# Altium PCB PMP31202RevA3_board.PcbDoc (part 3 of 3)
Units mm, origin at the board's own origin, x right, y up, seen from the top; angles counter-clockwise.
Board outline 156.21 x 130.81 mm, 4 copper layers (Top Layer, Layer 2, Layer 3, Bottom Layer), stack 1.671 mm thick; 198 components, 74 nets, 489 pads, 691 vias.
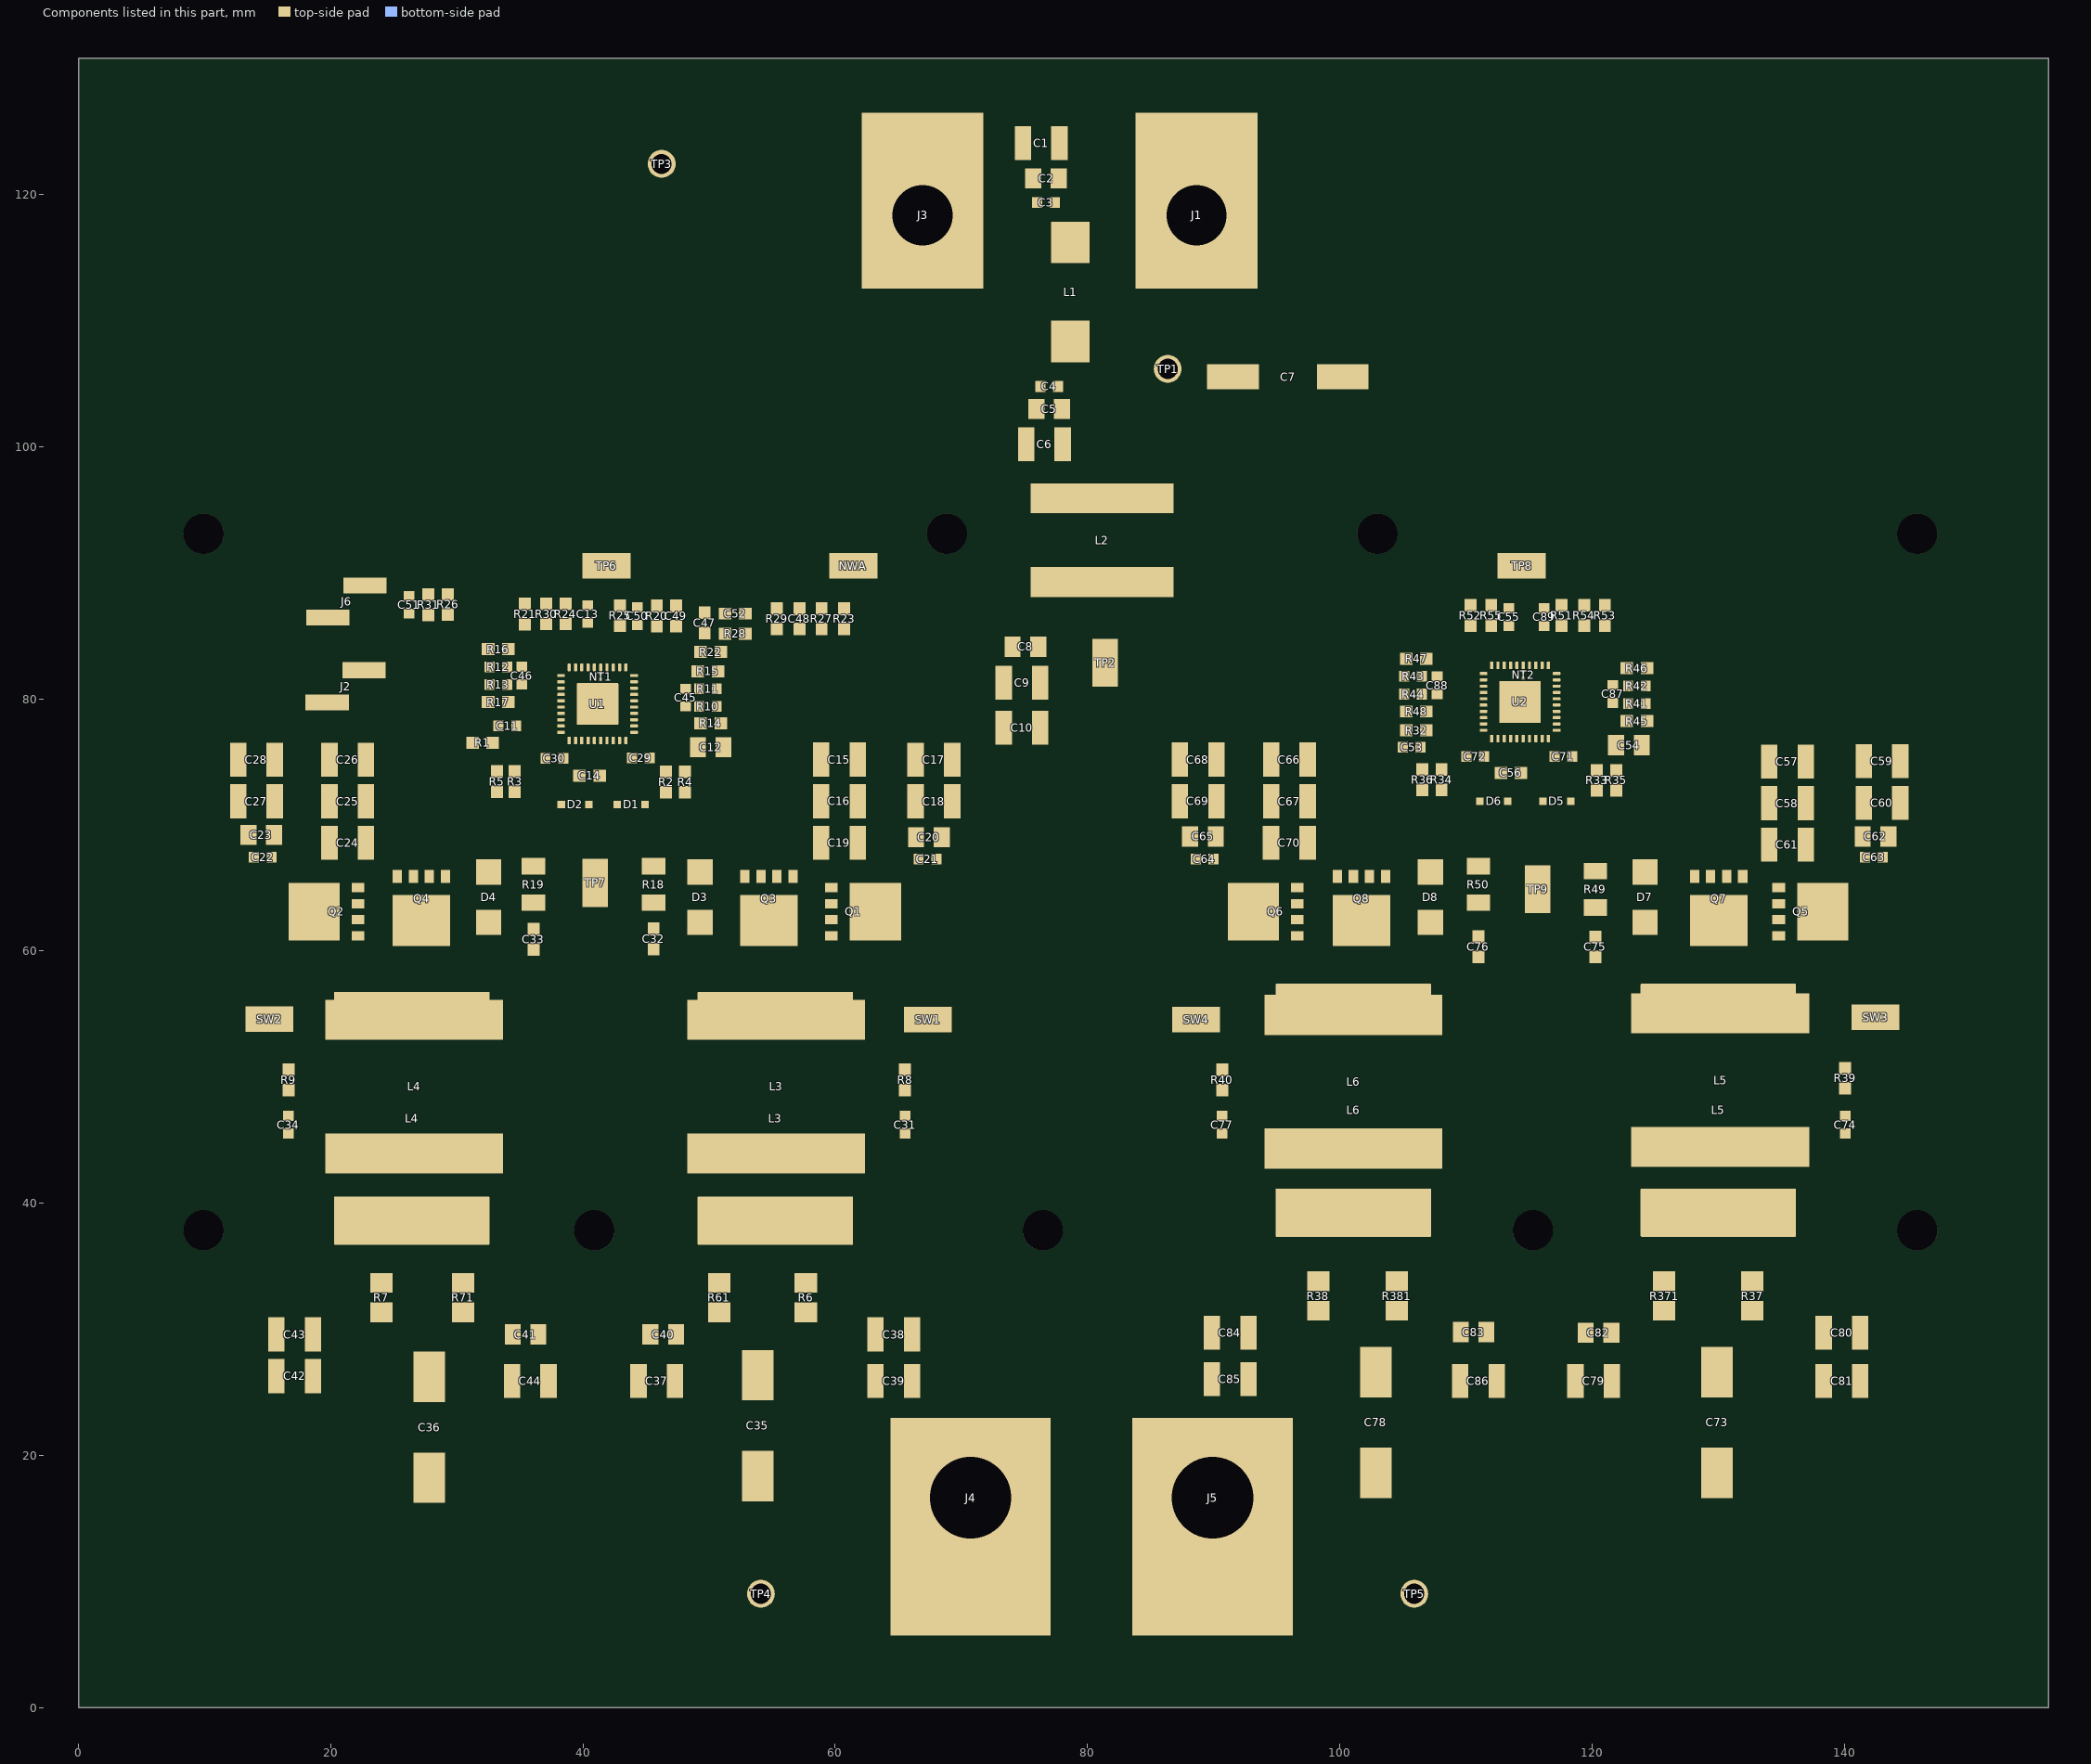
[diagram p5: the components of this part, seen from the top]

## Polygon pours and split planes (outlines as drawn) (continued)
NetC71_1 on Top Layer "TOP_LAYER_NETC71_1_P007" (solid, remove dead copper, pour order 7): 119.096,54.737 ccw(c121.636,54.737) 121.636,52.197 142.812,52.197 ccw(c142.812,54.737) 145.352,54.737 145.352,55.404 145.352,56.007 ccw(c142.812,56.007) 142.812,58.547 137.119,58.547 cw(c137.119,60.237) 135.429,60.237 135.429,65.119 ccw(c134.879,65.119) 134.879,65.669 134.666,65.669 ccw(c134.666,63.808) 133.35,65.124 132.917,64.691 cw(c132.207,65.402) 132.207,64.397 126.857,64.397 ccw(c126.857,63.123) 125.956,64.024 cw(c124.373,65.607) 124.373,63.368 123.822,63.368 ccw(c123.822,61.522) 121.975,61.522 121.975,60.882 cw(c121.285,60.882) 121.285,60.192 119.714,60.192 ccw(c119.714,59.574) 119.096,59.574
VOUT on Top Layer "TOP_LAYER_VOUT_P003" (solid, remove dead copper, pour order 3): 92.075,32.258 92.075,24.308 110.236,24.308 110.236,32.258
NetC77_2 on Top Layer "TOP_LAYER_NETC77_2_P005" (solid, remove dead copper, pour order 5): 92.057,34.435 93.468,33.024 108.071,33.024 110.226,35.179 110.226,45.247 108.991,46.482 93.27,46.482 92.057,45.269
NetC72_1 on Top Layer "TOP_LAYER_NETC72_1_P006" (solid, remove dead copper, pour order 6): 86.36,56.007 cw(c88.882,56.007) 88.882,58.529 94.54,58.529 ccw(c94.54,60.001) 96.012,60.001 96.012,63.815 cw(c96.459,63.815) 96.459,64.262 98.74,64.262 ccw(c98.74,64.562) 98.952,64.35 cw(c99.284,64.018) 99.284,64.487 106.46,64.487 cw(c106.46,61.947) 108.256,63.744 108.8,63.199 cw(c107.004,61.403) 109.544,61.403 109.544,60.999 ccw(c110.3,60.999) 110.3,60.242 111.473,60.242 cw(c111.473,59.04) 112.675,59.04 112.675,54.128 cw(c110.744,54.128) 110.744,52.197 88.265,52.197 cw(c88.265,54.102) 86.36,54.102
PGND on Top Layer "TOP_LAYER_PGND_P032" (solid, remove dead copper, pour order 32): 2.54,128.27 2.54,2.54 153.67,2.54 153.67,128.27
NetC29_1 on Top Layer "TOP_LAYER_NETC29_1_P031" (solid, remove dead copper, pour order 31): 68.834,52.197 ccw(c68.834,53.848) 70.485,53.848 70.485,56.007 ccw(c67.945,56.007) 67.945,58.547 61.722,58.547 cw(c61.722,60.01) 60.259,60.01 60.259,65.235 ccw(c59.825,65.235) 59.825,65.669 59.262,65.669 ccw(c59.262,64.768) 58.625,65.405 58.442,65.222 cw(c56.737,66.928) 56.737,64.516 52.548,64.516 ccw(c52.548,62.364) 51.026,63.886 cw(c49.777,65.134) 49.777,63.368 48.088,63.368 ccw(c48.088,62.374) 47.094,62.374 47.094,61.76 cw(c46.294,61.76) 46.294,60.96 45.118,60.96 ccw(c45.118,59.89) 44.048,59.89 44.048,54.737 ccw(c46.588,54.737) 46.588,52.197
AGND1 on Top Layer "TOP_LAYER_AGND1_P030" (solid, remove dead copper, pour order 30): 57.66,84.74 57.66,89.234 55.32,91.575 35.435,91.575 33.012,89.151 33.012,84.74
VIN on Top Layer "TOP_LAYER_VIN_P028" (solid, remove dead copper, pour order 28): 136.271,60.329 141.261,60.329 142.24,61.308 142.24,76.401 141.298,77.343 137.287,77.343 136.271,76.327
VIN on Top Layer "TOP_LAYER_VIN_P026" (solid, remove dead copper, pour order 26): 95.002,60.242 91.142,60.242 89.535,61.849 89.535,76.632 89.687,76.784 94.992,76.784 95.25,76.526 95.25,60.49
VIN on Top Layer "TOP_LAYER_VIN_P023" (solid, remove dead copper, pour order 23): 86.741,87.09 96.172,87.09 96.244,87.018 96.244,79.391 85.614,79.391 84.487,78.264 84.487,75.946 75.438,75.946 75.438,90.551 86.741,90.551
VIN on Top Layer "TOP_LAYER_VIN_P025" (solid, remove dead copper, pour order 25): 61.087,60.344 65.626,60.344 67.004,61.722 67.004,76.526 61.087,76.526
VOUT on Top Layer "TOP_LAYER_VOUT_P019" (solid, remove dead copper, pour order 19): 46.67,32.136 46.67,24.308 63.82,24.308 63.82,32.136
NetC31_2 on Top Layer "TOP_LAYER_NETC31_2_P017" (solid, remove dead copper, pour order 17): 62.974,46.001 63.82,45.155 63.82,34.737 61.971,32.888 47.993,32.888 46.67,34.212 46.67,45.165 47.506,46.001
NetC4_2 on Top Layer "TOP_LAYER_NETC4_2_P015" (solid, remove dead copper, pour order 15): 77.081,110.032 77.081,98.652 76.262,97.833 75.481,97.833 74.549,96.901 74.549,94.446 75.082,93.913 93.891,93.913 94.361,94.383 94.361,97.614 94.361,110.032 82.584,110.032
NetC1_1 on Top Layer "TOP_LAYER_NETC1_1_P013" (solid, remove dead copper, pour order 13): 77.089,126.229 77.089,114.103 78.99,112.202 93.98,112.202 93.98,128.27 79.13,128.27
VOUT on Top Layer "TOP_LAYER_VOUT_P012" (solid, remove dead copper, pour order 12): 17.861,32.136 17.861,24.257 35.052,24.257 35.052,32.136
NetC34_2 on Top Layer "TOP_LAYER_NETC34_2_P010" (solid, remove dead copper, pour order 10): 17.861,44.846 17.861,35.216 20.153,32.924 33.949,32.924 34.991,33.966 34.991,45.765 34.755,46.001 19.016,46.001
NetC30_1 on Top Layer "TOP_LAYER_NETC30_1_P009" (solid, remove dead copper, pour order 9): 20.267,52.262 13.754,52.262 cw(c13.754,53.76) 12.255,53.76 12.255,54.605 cw(c14.795,54.605) 12.999,56.401 14.782,58.184 cw(c16.578,56.388) 16.578,58.928 17.738,58.928 ccw(c17.738,61.468) 19.534,59.672 20.902,61.039 ccw(c19.106,62.835) 21.646,62.836 21.646,64.008 cw(c22.029,64.008) 21.653,64.083 cw(c22.082,64.087) 22.077,64.516 33.02,64.516 cw(c33.02,63.119) 34.417,63.119 34.417,61.627 ccw(c35.343,61.627) 35.343,60.701 36.068,60.701 cw(c36.068,59.258) 37.51,59.258 37.51,53.689 cw(c36.083,53.689) 36.083,52.262
VIN on Top Layer "TOP_LAYER_VIN_P008" (solid, remove dead copper, pour order 8): 20,60.35 20.701,61.052 20.701,65.742 20.701,76.504 14.782,76.504 14.782,61.214 15.646,60.35
PGND on Layer 3 "LAYER_3_PGND_P061" (solid, remove dead copper, pour order 61): 2.49,128.18 2.49,2.54 153.67,2.54 153.67,128.27
NetC4_2 on Layer 3 "LAYER_3_NETC4_2_P059" (solid, remove dead copper, pour order 59): 77.068,110.032 77.068,98.652 76.249,97.833 75.468,97.833 74.536,96.901 74.536,94.446 75.07,93.913 93.878,93.913 94.348,94.383 94.348,97.614 94.348,110.032 82.571,110.032
NetC1_1 on Layer 3 "LAYER_3_NETC1_1_P057" (solid, remove dead copper, pour order 57): 77.089,126.229 77.089,114.103 78.99,112.202 93.98,112.202 93.98,128.27 79.13,128.27
NetC29_1 on Layer 3 "LAYER_3_NETC29_1_P014" (solid, remove dead copper, pour order 14): 52.452,59.69 cw(c52.449,60.196) 51.942,60.196 51.942,64.201 cw(c52.456,64.201) 52.456,64.715 57.075,64.715 cw(c57.075,64.26) 57.53,64.26 57.53,60.303 cw(c56.868,60.352) 56.819,59.69
NetC30_1 on Layer 3 "LAYER_3_NETC30_1_P020" (solid, remove dead copper, pour order 20): 24.919,59.7 cw(c24.916,60.206) 24.41,60.206 24.41,64.211 cw(c24.924,64.211) 24.924,64.725 29.543,64.725 cw(c29.543,64.27) 29.998,64.27 29.998,60.313 cw(c29.336,60.362) 29.287,59.7
NetC72_1 on Layer 3 "LAYER_3_NETC72_1_P049" (solid, remove dead copper, pour order 49): 99.418,59.776 cw(c99.414,60.282) 98.908,60.282 98.908,64.288 cw(c99.422,64.288) 99.422,64.802 104.041,64.802 cw(c104.041,64.346) 104.496,64.346 104.496,60.389 cw(c103.834,60.438) 103.785,59.776
NetC71_1 on Layer 3 "LAYER_3_NETC71_1_P051" (solid, remove dead copper, pour order 51): 127.756,59.692 cw(c127.756,60.198) 127.25,60.198 127.25,64.203 cw(c127.764,64.203) 127.764,64.717 132.383,64.717 cw(c132.383,64.262) 132.838,64.262 132.838,60.305 cw(c132.176,60.354) 132.127,59.692
VOUT on Layer 3 "LAYER_3_VOUT_P055" (solid, remove dead copper, pour order 55): 17.861,31.623 17.861,2.54 139.7,2.54 139.7,31.623
VIN on Layer 3 "LAYER_3_VIN_P054" (solid, remove dead copper, pour order 54): 96.147,87.09 96.244,86.993 96.244,79.391 85.614,79.391 84.487,78.264 84.487,70.223 89.611,70.223 89.611,76.708 95.25,76.708 95.25,70.223 134.059,70.223 134.059,77.343 142.24,77.343 142.24,50.504 12.768,50.504 12.768,76.708 21.288,76.708 21.288,70.223 59.125,70.223 59.125,76.776 67.004,76.776 67.004,70.223 75.481,70.223 75.481,87.09
NetC4_2 on Bottom Layer "BOTTOM_LAYER_NETC4_2_P022" (solid, remove dead copper, pour order 22): 77.068,110.032 77.068,98.652 76.249,97.833 75.468,97.833 74.536,96.901 74.536,94.446 75.07,93.913 93.878,93.913 94.348,94.383 94.348,97.614 94.348,110.032 82.571,110.032
NetC1_1 on Bottom Layer "BOTTOM_LAYER_NETC1_1_P021" (solid, remove dead copper, pour order 21): 77.089,126.229 77.089,114.103 78.99,112.202 93.98,112.202 93.98,128.27 79.13,128.27
VIN on Bottom Layer "BOTTOM_LAYER_VIN_P027" (solid, remove dead copper, pour order 27): 90.739,60.639 90.739,65.856 95.483,65.856 95.483,60.639
VIN on Bottom Layer "BOTTOM_LAYER_VIN_P029" (solid, remove dead copper, pour order 29): 135.964,60.526 135.964,65.743 140.709,65.743 140.709,60.526
VIN on Bottom Layer "BOTTOM_LAYER_VIN_P033" (solid, remove dead copper, pour order 33): 60.856,60.526 60.856,65.743 65.601,65.743 65.601,60.526
VIN on Bottom Layer "BOTTOM_LAYER_VIN_P034" (solid, remove dead copper, pour order 34): 16.254,60.501 16.254,65.718 20.999,65.718 20.999,60.501
VOUT on Bottom Layer "BOTTOM_LAYER_VOUT_P042" (solid, remove dead copper, pour order 42): 120.875,31.75 139.108,31.75 139.108,24.257 120.947,24.257
VOUT on Bottom Layer "BOTTOM_LAYER_VOUT_P037" (solid, remove dead copper, pour order 37): 92.118,31.75 92.118,24.308 110.279,24.308 110.279,31.75
VOUT on Bottom Layer "BOTTOM_LAYER_VOUT_P036" (solid, remove dead copper, pour order 36): 46.627,31.623 46.627,24.308 63.777,24.308 63.777,31.623 60.536,31.623
VOUT on Bottom Layer "BOTTOM_LAYER_VOUT_P035" (solid, remove dead copper, pour order 35): 17.866,31.496 17.866,24.257 35.057,24.257 35.057,31.496
PGND on Bottom Layer "BOTTOM_LAYER_PGND_P060" (solid, remove dead copper, pour order 60): 2.49,128.27 153.67,128.27 153.67,2.54 2.578,2.54
NetC71_1 on Bottom Layer "BOTTOM_LAYER_NETC71_1_P058" (solid, remove dead copper, pour order 58): 119.032,54.737 ccw(c121.572,54.737) 121.572,52.197 142.748,52.197 ccw(c142.748,54.737) 145.288,54.737 145.288,55.404 145.288,56.007 ccw(c142.748,56.007) 142.748,58.547 137.055,58.547 cw(c137.055,60.237) 135.365,60.237 135.365,65.119 ccw(c134.815,65.119) 134.815,65.669 134.602,65.669 ccw(c134.602,63.808) 133.286,65.124 132.853,64.691 cw(c132.143,65.402) 132.143,64.397 126.793,64.397 ccw(c126.793,63.123) 125.892,64.024 cw(c124.309,65.607) 124.309,63.368 123.758,63.368 ccw(c123.758,61.522) 121.911,61.522 121.911,60.882 cw(c121.221,60.882) 121.221,60.192 119.65,60.192 ccw(c119.65,59.574) 119.032,59.574
NetC72_1 on Bottom Layer "BOTTOM_LAYER_NETC72_1_P056" (solid, remove dead copper, pour order 56): 86.344,56.007 cw(c88.866,56.007) 88.866,58.529 94.524,58.529 ccw(c94.524,60.001) 95.996,60.001 95.996,63.815 cw(c96.443,63.815) 96.443,64.262 98.724,64.262 ccw(c98.724,64.562) 98.936,64.35 cw(c99.268,64.018) 99.268,64.487 106.443,64.487 cw(c106.443,61.947) 108.239,63.744 108.784,63.199 cw(c106.988,61.403) 109.528,61.403 109.528,60.999 ccw(c110.284,60.999) 110.284,60.242 111.457,60.242 cw(c111.457,59.04) 112.659,59.04 112.659,54.128 cw(c110.728,54.128) 110.728,52.197 88.249,52.197 cw(c88.249,54.102) 86.344,54.102
NetC29_1 on Bottom Layer "BOTTOM_LAYER_NETC29_1_P047" (solid, remove dead copper, pour order 47): 68.835,52.197 ccw(c68.835,53.848) 70.486,53.848 70.486,56.007 ccw(c67.946,56.007) 67.946,58.547 61.723,58.547 cw(c61.723,60.01) 60.26,60.01 60.26,65.235 ccw(c59.826,65.235) 59.826,65.669 59.263,65.669 ccw(c59.263,64.768) 58.626,65.405 58.443,65.222 cw(c56.738,66.928) 56.738,64.516 52.548,64.516 ccw(c52.548,62.364) 51.027,63.886 cw(c49.778,65.134) 49.778,63.368 48.089,63.368 ccw(c48.089,62.374) 47.095,62.374 47.095,61.76 cw(c46.295,61.76) 46.295,60.96 45.119,60.96 ccw(c45.119,59.89) 44.049,59.89 44.049,54.737 ccw(c46.589,54.737) 46.589,52.197
NetC30_1 on Bottom Layer "BOTTOM_LAYER_NETC30_1_P044" (solid, remove dead copper, pour order 44): 20.271,52.241 13.758,52.241 cw(c13.758,53.74) 12.259,53.74 12.259,54.584 cw(c14.799,54.584) 13.003,56.38 14.787,58.163 cw(c16.583,56.367) 16.583,58.907 17.743,58.907 ccw(c17.743,61.447) 19.539,59.651 20.906,61.019 ccw(c19.11,62.815) 21.65,62.815 21.65,63.987 cw(c22.034,63.987) 21.658,64.062 cw(c22.086,64.067) 22.082,64.495 33.024,64.495 cw(c33.024,63.098) 34.421,63.098 34.421,61.606 ccw(c35.347,61.606) 35.347,60.68 36.072,60.68 cw(c36.072,59.238) 37.515,59.238 37.515,53.668 cw(c36.087,53.668) 36.087,52.241
NetC30_1 on Layer 2 "LAYER_2_NETC30_1_P052" (solid, remove dead copper, pour order 52): 24.919,59.7 cw(c24.916,60.206) 24.41,60.206 24.41,64.211 cw(c24.924,64.211) 24.924,64.725 29.543,64.725 cw(c29.543,64.27) 29.998,64.27 29.998,60.313 cw(c29.336,60.362) 29.287,59.7
NetC29_1 on Layer 2 "LAYER_2_NETC29_1_P048" (solid, remove dead copper, pour order 48): 52.448,59.701 cw(c52.444,60.207) 51.938,60.207 51.938,64.213 cw(c52.452,64.213) 52.452,64.727 57.071,64.727 cw(c57.071,64.271) 57.526,64.271 57.526,60.314 cw(c56.864,60.363) 56.815,59.701
NetC72_1 on Layer 2 "LAYER_2_NETC72_1_P043" (solid, remove dead copper, pour order 43): 99.433,59.782 cw(c99.43,60.288) 98.924,60.288 98.924,64.293 cw(c99.438,64.293) 99.438,64.807 104.057,64.807 cw(c104.057,64.352) 104.512,64.352 104.512,60.395 cw(c103.85,60.444) 103.8,59.782
NetC71_1 on Layer 2 "LAYER_2_NETC71_1_P041" (solid, remove dead copper, pour order 41): 127.763,59.692 cw(c127.76,60.198) 127.254,60.198 127.254,64.203 cw(c127.768,64.203) 127.768,64.717 132.387,64.717 cw(c132.387,64.262) 132.842,64.262 132.842,60.305 cw(c132.18,60.354) 132.131,59.692
VIN on Layer 2 "LAYER_2_VIN_P018" (solid, remove dead copper, pour order 18): 135.99,60.552 135.99,65.769 140.734,65.769 140.734,60.552
VIN on Layer 2 "LAYER_2_VIN_P045" (solid, remove dead copper, pour order 45): 90.752,60.501 90.752,65.718 95.497,65.718 95.497,60.501
VIN on Layer 2 "LAYER_2_VIN_P050" (solid, remove dead copper, pour order 50): 60.831,60.552 60.831,65.769 65.576,65.769 65.576,60.552
VIN on Layer 2 "LAYER_2_VIN_P046" (solid, remove dead copper, pour order 46): 16.317,60.569 16.317,65.786 21.061,65.786 21.061,60.569
PGND on Layer 2 "LAYER_2_PGND_P053" (solid, remove dead copper, pour order 53): 2.54,128.27 153.67,128.27 153.67,2.54 2.54,2.54

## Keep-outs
Keep-Out Layer:
  text ".Layer_Name" at 8.306,-53.556 h1.52

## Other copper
Top Layer:
  pour cut-out: 135.63,65.58 136.271,65.58 136.271,60.293 135.504,60.293
  pour cut-out: 127.473,65.278 132.526,65.278 132.526,64.769 127.448,64.769
  pour cut-out: 99.181,65.278 104.277,65.278 104.277,64.762 99.244,64.762
  pour cut-out: 95.377,65.913 95.377,65.914 95.996,65.914 95.996,63.754 95.412,63.754
  pour cut-out: 112.649,77.851 112.649,81.431 112.014,81.431 112.014,77.851
  pour cut-out: 115.951,81.534 115.951,78.081 116.573,78.081 116.573,81.431
  pour cut-out: 112.027,81.431 112.027,82.057 116.573,82.057 116.573,81.431
  pour cut-out: 112.027,78.081 112.027,77.483 116.573,77.483 116.573,78.081
  pour cut-out: 52.305,65.377 52.305,64.528 56.896,64.528 56.896,65.362
  pour cut-out: 60.305,60.636 60.305,65.669 60.958,65.669 60.958,60.779
  pour cut-out: 20.745,60.823 21.462,60.823 21.462,65.786 20.745,65.786
  pour cut-out: 24.628,65.233 24.628,64.516 29.591,64.516 29.591,65.233
  pour cut-out: 42.897,76.979 43.747,76.979 43.747,82.13 42.902,82.13
  pour cut-out: 38.579,76.979 39.429,76.979 39.429,82.13 38.584,82.13
  pour cut-out: 38.625,82.198 38.625,81.348 43.776,81.348 43.776,82.193
  pour cut-out: 38.608,77.851 38.608,77.001 43.759,77.001 43.759,77.846
  text ".Layer_Name" at 8.306,-53.556 h1.52
Bottom Layer:
  text ".Layer_Name" at 8.306,-53.556 h1.52

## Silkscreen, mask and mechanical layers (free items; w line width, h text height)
Top Overlay:
  text "GND" at 52.324,120.536 h2
  text "IN" at 97.79,119.634 h2
  text "'.PRJ_Number'.PCB_Rev" at 13.843,10.795 h2
  text "VOUT" at 40.24,8.636 h2
  text "GND" at 111.752,8.255 h2
  text ".Layer_Name" at 8.306,-53.556 h1.52
Bottom Overlay:
  lines w0.3: 3.029,26.905 3.029,101.905 153.029,101.905 153.029,26.905 3.029,26.905
  text ".Layer_Name" at 8.306,-53.556 h1.52
Top Paste:
  text ".Layer_Name" at 8.306,-53.556 h1.52
Bottom Paste:
  text ".Layer_Name" at 8.306,-53.556 h1.52
Top Solder:
  rectangle: 68.527,59.897 73.292,64.753
  text ".Layer_Name" at 8.306,-53.556 h1.52
  text ".Layer_Name" at 8.306,-53.556 h1.52
Bottom Solder:
  region: 1.169,103.81 154.737,103.81 154.737,25.298 1.168,25.298
  text "'.PRJ_Number'.PCB_Rev" at 35.177,6.477 h3
  text ".Layer_Name" at 8.306,-53.556 h1.52
Drill Guide:
  text ".Layer_Name" at 8.306,-53.556 h1.52
M1 Board Outline:
  the board outline again, w0.254
  text ".Layer_Name" at 8.306,-53.556 h1.52
M2 Board Dimensions:
  rectangle: 182.65,-37.735 185.825,-34.56
  rectangle: 185.825,-40.91 195.35,-37.735
  lines w0.178: 182.65,-37.735 208.05,-37.735 ; 185.825,-40.91 185.825,-34.56 ; 189,-40.91 189,-34.56 ; 195.35,-40.91 195.35,-34.56 ; 201.7,-40.91 201.7,-34.56 ; 182.65,-40.91 208.05,-40.91 208.05,-34.56 182.65,-34.56 182.65,-40.91
  text "'.Print_Date' '.Print_Time'" at 98.044,134.318 h5
  text ".Layer_Name" at 8.306,-53.556 h1.52
M3 3D STEP Top:
  text ".Layer_Name" at 8.306,-53.556 h1.52
M4 3D STEP Bottom:
  text ".Layer_Name" at 8.306,-53.556 h1.52
M5 Assembly Top:
  lines w0.254: -13.767,-55.376 153.873,-55.376 ; -13.767,-50.212 153.924,-50.212 ; -13.767,-45.047 -13.767,-60.541 87.96,-60.541 153.924,-60.541 153.924,-45.047 -13.754,-45.047 -13.754,-60.541 26.264,-60.541 ; 48.844,-60.541 48.844,-45.047 ; 81.026,-50.212 81.026,-45.047 ; 102.362,-50.212 102.362,-45.047 ; 118.161,-60.706 118.161,-55.554
  text "COMPONENTS MARKED 'DNP' SHOULD NOT BE POPULATED." at 212.949,-38.84 h1.52
  text "ASSEMBLY VARIANT:" at 212.936,-41.774 h1.52
  text ".VariantName" at 239.251,-41.774 h1.52
  text "PCB VIEWED FROM TOP SIDE" at -12.154,-48.404 h1.52
  text "BOARD #:" at 50.749,-48.404 h1.52
  text ".PRJ_Number" at 64.605,-48.404 h1.52
  text "REV:" at 86.055,-48.404 h1.52
  text ".PCB_Rev" at 93.459,-48.404 h1.52
  text "SVN REV:" at 107.34,-48.404 h1.52
  text ".VersionControl_RevNumber" at 120.193,-48.404 h1.52
  text "TID #:" at 50.749,-53.569 h1.52
  text ".TID" at 64.605,-53.569 h1.52
  text "PLOT NAME =" at -12.154,-58.784 h1.52
  text ".plot_File_Name" at 8.306,-58.784 h1.52
  text "GENERATED    :" at 50.8,-58.784 h1.52
  text ".Print_Date" at 72.885,-58.784 h1.52
  text ".Print_Time" at 91.402,-58.784 h1.52
  text "TEXAS INSTRUMENTS" at 123.52,-58.784 h1.52
M6 Assembly Bottom:
  lines w0.254: -13.779,-50.224 153.911,-50.224 ; -13.729,-55.389 153.911,-55.389 ; 21.984,-60.719 21.984,-55.567 ; 37.782,-50.224 37.782,-45.06 ; 59.118,-50.224 59.118,-45.06 ; 91.3,-60.554 91.3,-45.06 ; 113.881,-60.554 153.899,-60.554 153.899,-45.06 -13.779,-45.06 -13.779,-60.554 52.184,-60.554 153.911,-60.554 153.911,-45.06
  text "COMPONENTS MARKED 'DNP' SHOULD NOT BE POPULATED." at 252.65,-29.75 h1.52
  text ".VariantName" at 226.123,-32.774 h1.52
  text "ASSEMBLY VARIANT:" at 252.514,-32.774 h1.52
  text ".VersionControl_RevNumber" at 19.952,-48.417 h1.52
  text "SVN REV:" at 32.804,-48.417 h1.52
  text ".PCB_Rev" at 46.685,-48.417 h1.52
  text "REV:" at 54.089,-48.417 h1.52
  text ".PRJ_Number" at 75.54,-48.417 h1.52
  text "BOARD #:" at 89.395,-48.417 h1.52
  text "PCB VIEWED FROM BOTTOM SIDE" at 152.298,-48.417 h1.52
  text ".TID" at 75.54,-53.581 h1.52
  text "TID #:" at 89.395,-53.581 h1.52
  text "TEXAS INSTRUMENTS" at 16.624,-58.797 h1.52
  text ".Print_Time" at 48.743,-58.797 h1.52
  text ".Print_Date" at 67.259,-58.797 h1.52
  text "GENERATED    :" at 89.344,-58.797 h1.52
  text ".plot_File_Name" at 131.839,-58.797 h1.52
  text "PLOT NAME =" at 152.298,-58.797 h1.52
M9 Title Sheet:
  drawing of 57 lines, arcs and shapes, not listed
  text "1" at 12.442,172.377 h1.78
  text "2" at 75.832,172.377 h1.78
  text "3" at 139.061,172.377 h1.78
  text "4" at 202.73,172.377 h1.78
  text "5" at 266.205,172.377 h1.78
  text "6" at 329.832,172.377 h1.78
  text "A" at -16.929,143.345 h1.78
  text "A" at 358.991,143.345 h1.78
  text "B" at -16.929,82.893 h1.78
  text "B" at 358.991,82.893 h1.78
  text "C" at -16.929,22.568 h1.78
  text "C" at 358.991,22.568 h1.78
  text "PROJECT TITLE:" at 281.775,-24.701 h1.14
  text ".PRJ_Title" at 283.045,-28.088 h1.78
  text "DESIGNED FOR:" at 281.775,-32.347 h1.14
  text ".PRJ_Customer" at 283.045,-35.903 h1.78
  text "D" at -16.929,-37.63 h1.78
  text "D" at 358.991,-37.63 h1.78
  text "FILE NAME:" at 281.775,-39.967 h1.14
  text ".PCB_File_Name_No_Path" at 283.045,-43.015 h1.78
  text "Texas Instruments (TI) and/or its licensors do not warrant the accuracy or completeness of this specification" at 155.55,-47.126 h1.14
  text "ENGINEER:" at 281.775,-47.333 h1.14
  text "LAYOUT BY:" at 320.002,-47.333 h1.14
  text "or any information contained therein. TI and/or its licensors do not warrant that this design will meet" at 154.407,-49.987 h1.14
  text ".PRJ_Engineer" at 283.045,-51.27 h1.78
  text ".PCB_Layout" at 321.285,-51.27 h1.78
  text "the specifications, will be suitable for your application or fit for any particular purpose, or will operate in" at 154.407,-52.849 h1.14
  text ".Layer_Name" at 8.306,-53.556 h1.52
  text "ALTIUM DESIGNER VERSION:" at 320.002,-55.207 h1.14
  text "an implementation. TI and/or its licensors do not warrant that the design is production worthy. You should" at 154.407,-55.711 h1.14
  text "completely validate and test your design implementation to confirm the system functionality for your application." at 155.55,-58.572 h1.14
  text ".print_Scale" at 283.045,-58.593 h1.78
  text ".Application_BuildNumber" at 321.285,-58.593 h1.78
  text "1" at 12.442,-63.843 h1.78
  text "2" at 75.832,-63.843 h1.78
  text "3" at 139.061,-63.843 h1.78
  text "4" at 202.73,-63.843 h1.78
  text "5" at 266.205,-63.843 h1.78
  text "6" at 329.832,-63.843 h1.78
M10 Fab Notes:
  drawing of 189 lines, arcs and shapes, not listed
  text "DESIGN INFORMATION" at 308.153,129.697 h1.52
  text "MIN. TRACK WIDTH:" at 291.781,126.341 h1.52
  text "8" at 319.626,126.341 h1.52
  text "MIL" at 323.557,126.341 h1.52
  text "MIN. CLEARANCE:" at 291.781,123.188 h1.52
  text "0.2" at 318.102,123.188 h1.52
  text "mm" at 323.557,123.188 h1.52
  text "MIN. VIA PAD SIZE:" at 291.781,120.035 h1.52
  text "24" at 318.864,120.035 h1.52
  text "MIL" at 323.557,120.035 h1.52
  text "0.05mm (2MIL)" at 309.434,116.736 h1.52
  text "MINIMUM ANNULAR RING" at 283.419,116.527 h1.52
  text "EXTERNAL" at 327.418,116.527 h1.52
  text "PER" at 288.499,113.73 h1.52
  text "IPC-D-275 CLASS 2 LEVEL C" at 294.087,113.73 h1.52
  text "MIL, HOLES" at 331.888,111.178 h1.52
  text "+/-" at 321.92,110.959 h1.52
  text "+/-" at 343.611,110.959 h1.52
  text "REGISTRATION TOLERANCES:" at 283.419,110.932 h1.52
  text "METAL" at 313.893,110.932 h1.52
  text "5" at 328.529,110.933 h1.52
  text "3" at 349.687,110.933 h1.52
  text "MIL" at 352.64,110.932 h1.52
  text "HOLE SIZE TOLERANCE (UNLESS OTHERWISE SPECIFIED):" at 283.419,108.435 h1.52
  text "+/-" at 343.611,108.362 h1.52
  text "3" at 349.687,108.335 h1.52
  text "MIL" at 352.64,108.335 h1.52
  text "MATERIAL:" at 281.52,104.839 h1.52
  text "FR-4 High Tg" at 306.576,101.574 h1.52
  text "X" at 302.907,101.372 h1.52
  text "FR-408" at 292.213,101.257 h1.52
  text "OTHER" at 330.008,101.257 h1.52
  text "62 MIL (1.6mm) +/-10%" at 300.344,97.624 h1.52
  text "X" at 297.293,97.562 h1.52
  text "THICKNESS:" at 283.419,97.415 h1.52
  text "OTHER" at 332.98,97.415 h1.52
  text "TOLERANCE:" at 283.419,93.902 h1.52
  text "X" at 304.964,93.902 h1.52
  text "ANSI IPC-6012 TYPE 3 CLASS 2" at 309.486,93.902 h1.52
  text "OTHER +/-" at 309.485,90.239 h1.52
  text "BOW & TWIST:" at 283.419,86.552 h1.52
  text "X" at 304.964,86.552 h1.52
  text "ANSI IPC-6012 TYPE 3 CLASS 2" at 309.486,86.552 h1.52
  text "OTHER +/-" at 309.485,82.826 h1.52
  text "DRILLING:" at 281.52,79.508 h1.52
  text "NC_DRILL FILES" at 326.249,76.836 h1.52
  text "REFERENCE:" at 283.419,76.736 h1.52
  text "X" at 300.113,76.734 h1.52
  text "AS SHOWN" at 304.634,76.736 h1.52
  text "X" at 322.998,76.736 h1.52
  text "OTHER" at 333.818,73.123 h1.52
  text "PTH COPPER THICKNESS:" at 283.411,73.033 h1.52
  text "X" at 312.347,73.033 h1.52
  text "20-30 um" at 315.598,73.033 h1.52
  text "BOARD FINISH:" at 281.52,69.284 h1.52
  text "SILKSCREEN:" at 285.462,66.487 h1.52
  text "X" at 309.79,66.487 h1.52
  text "TOP" at 312.762,66.487 h1.52
  text "X" at 322.744,66.487 h1.52
  text "BOTTOM" at 325.741,66.487 h1.52
  text "SILKSCREEN COLOR:" at 285.462,62.545 h1.52
  text "X" at 309.765,62.545 h1.52
  text "WHITE" at 312.762,62.545 h1.52
  text "OTHER" at 325.741,62.545 h1.52
  text "X" at 313.092,58.902 h1.52
  text "GREEN" at 316.089,58.902 h1.52
  text "OTHER" at 331.786,58.902 h1.52
  text "SOLDER RESIST COLOR:" at 285.462,58.727 h1.52
  text "X" at 313.092,54.984 h1.52
  text "MATTE" at 316.089,54.984 h1.52
  text "SEMI-GLOSS" at 331.775,54.967 h1.52
  text "IMMERSION GOLD (ENIG)" at 308.469,50.595 h1.52
  text "ENEPIG" at 342.443,50.412 h1.52
  text "SURFACE FINISH:" at 281.52,50.386 h1.52
  text "X" at 303.948,50.386 h1.52
  text "IMM. TIN/SILVER OR EQUIV" at 289.89,46.899 h1.52
  text "OTHER" at 326.249,46.799 h1.52
  text "ARRAY/PANEL:" at 281.52,42.852 h1.52
  text "CUT AND TRIM PER M1 BOARD OUTLINE" at 308.469,42.643 h1.52
  text "N.C. ROUTE" at 308.469,39.19 h1.52
  text "X" at 325.945,39.19 h1.52
  text "V. SCORE" at 330.466,39.19 h1.52
  text "CERTIFICATION:" at 281.52,35.91 h1.52
  text "MATERIALS AND WORKMANSHIP FOR ALL PCBS" at 299.935,35.91 h1.52
  text "TO MEET OR EXCEED THE REQUIREMENTS OF:" at 299.935,33.521 h1.52
  text "X" at 290.728,30.253 h1.52
  text "ANSI IPC-A-600F CLASS ->" at 293.979,30.253 h1.52
  text "X" at 335.838,30.253 h1.52
  text "2" at 338.632,30.253 h1.52
  text "1" at 330.631,30.215 h1.52
  text "3" at 347.623,30.215 h1.52
  text "X" at 311.352,26.502 h1.52
  text "RoHS" at 314.603,26.502 h1.52
  text "OTHER" at 330.971,26.502 h1.52
  text "PER ORDER" at 341.057,26.502 h1.52
  text "ALL BOARDS MUST MEET OR EXCEED UL94-V0 REQUIREMENTS." at 282.219,22.595 h1.52
  text "PCB MUST BEAR THE UL94V-0 UL REGISTERED MATERIAL ID NUMBER" at 282.219,19.647 h1.52
  text "ADDITIONAL REQUIREMENTS:" at 281.52,15.344 h1.52
  text "MICROSECTION:" at 283.419,12.623 h1.52
  text "YES" at 306.425,12.623 h1.52
  text "REQUIRED" at 328.307,8.957 h1.52
  text "BARE BOARD ELEC. TEST:" at 283.419,8.884 h1.52
  text "NONE" at 316.585,8.884 h1.52
  text "X" at 325.31,8.884 h1.52
  text "PER ORDER" at 343.343,8.884 h1.52
  text "XX MIL VIAS REQUIRE NON-CONDUCTIVE FILL AND PLANARIZE" at 287.69,3.678 h1.5
  text "XX MIL VIAS REQUIRE CONDUCTIVE FILL AND PLANARIZE" at 287.893,1.037 h1.52
  text "OUTER XX MIL TRACES REQUIRE 50 OHM SINGLE-ENDED IMPEDANCE" at 287.868,-3.113 h1.47
  text "LAYER 2 & 3 (INNER LAYERS) XX MIL WIDE, XX MIL SPACE / TRACES REQUIRE 100 OHM DIFFERENTIAL IMPEDANCE" at 287.665,-9.1 h1.52
  text ".Layer_Name" at 8.306,-53.556 h1.52
M11 Gerber Information:
  lines w0.254: -13.767,-55.376 153.873,-55.376 ; -13.767,-50.212 153.924,-50.212 ; -13.767,-45.047 -13.767,-60.541 87.96,-60.541 153.924,-60.541 153.924,-45.047 -13.754,-45.047 -13.754,-60.541 26.264,-60.541 ; 48.844,-60.541 48.844,-45.047 ; 81.026,-50.212 81.026,-45.047 ; 102.362,-50.212 102.362,-45.047 ; 118.161,-60.706 118.161,-55.554
  text "ALL ARTWORK VIEWED FROM TOP SIDE" at -12.154,-48.404 h1.52
  text "BOARD #:" at 50.749,-48.404 h1.52
  text ".PRJ_Number" at 64.605,-48.404 h1.52
  text "REV:" at 86.055,-48.404 h1.52
  text ".PCB_Rev" at 93.459,-48.404 h1.52
  text "SVN REV:" at 107.34,-48.404 h1.52
  text ".VersionControl_RevNumber" at 120.193,-48.404 h1.52
  text "LAYER NAME =" at -12.154,-53.556 h1.52
  text "TID #:" at 50.749,-53.569 h1.52
  text ".TID" at 64.605,-53.569 h1.52
  text "PLOT NAME =" at -12.154,-58.784 h1.52
  text ".plot_File_Name" at 8.306,-58.784 h1.52
  text "GENERATED    :" at 50.8,-58.784 h1.52
  text ".Print_Date" at 72.885,-58.784 h1.52
  text ".Print_Time" at 91.402,-58.784 h1.52
  text "TEXAS INSTRUMENTS" at 123.52,-58.784 h1.52
M12 Stackup:
  drawing of 295 lines, arcs and shapes, not listed
  text "Layer" at 242.769,162.56 h1.52
  text "Name" at 253.181,162.56 h1.52
  text "Material" at 276.796,162.56 h1.52
  text "Thickness" at 298.635,162.56 h1.52
  text "Constant" at 315.14,162.56 h1.52
  text "Board Layer Stack" at 329.615,162.56 h1.52
  text "Top Overlay" at 253.181,159.512 h1.52
  text "Top Solder" at 253.181,156.464 h1.52
  text "Solder Resist" at 276.796,156.464 h1.52
  text "0.40mil" at 298.635,156.464 h1.52
  text "3.5" at 315.14,156.464 h1.52
  text "1" at 242.769,153.416 h1.52
  text "Top Layer" at 253.181,153.416 h1.52
  text "1.40mil" at 298.635,153.416 h1.52
  text "Dielectric 2" at 253.181,150.368 h1.52
  text "PP-006" at 276.796,150.368 h1.52
  text "16.14mil" at 298.635,150.368 h1.52
  text "4.1" at 315.14,150.368 h1.52
  text "2" at 242.769,147.32 h1.52
  text "Layer 2" at 253.181,147.32 h1.52
  text "CF-004" at 276.796,147.32 h1.52
  text "1.38mil" at 298.635,147.32 h1.52
  text "Dielectric3" at 253.181,144.272 h1.52
  text "FR-4" at 276.796,144.272 h1.52
  text "27.95mil" at 298.635,144.272 h1.52
  text "4.8" at 315.14,144.272 h1.52
  text "3" at 242.769,141.224 h1.52
  text "Layer 3" at 253.181,141.224 h1.52
  text "CF-004" at 276.796,141.224 h1.52
  text "1.38mil" at 298.635,141.224 h1.52
  text "Dielectric 3" at 253.181,138.176 h1.52
  text "PP-006" at 276.796,138.176 h1.52
  text "16.14mil" at 298.635,138.176 h1.52
  text "4.1" at 315.14,138.176 h1.52
  text "4" at 242.769,135.128 h1.52
  text "Bottom Layer" at 253.181,135.128 h1.52
  text "1.40mil" at 298.635,135.128 h1.52
  text "Bottom Solder" at 253.181,132.08 h1.52
  text "Solder Resist" at 276.796,132.08 h1.52
  text "0.40mil" at 298.635,132.08 h1.52
  text "3.5" at 315.14,132.08 h1.52
  text "Bottom Overlay" at 253.181,129.032 h1.52
  text ".Layer_Name" at 8.306,-53.556 h1.52
M13 Component Bodies Top:
  text ".Layer_Name" at 8.306,-53.556 h1.52
M14 Component Bodies Bottom:
  text ".Layer_Name" at 8.306,-53.556 h1.52
M15 Courtyards Top:
  text ".Layer_Name" at 8.306,-53.556 h1.52
M16 Courtyards Bottom:
  text ".Layer_Name" at 8.306,-53.556 h1.52
Drill Drawing:
  circle w0.254: c183.218,49.562 r0.703
  lines w0.254: 182.515,52.022 183.921,52.022 183.921,53.427 182.515,53.427 182.515,52.022 ; 182.515,55.887 183.218,55.184 183.921,55.887 183.218,56.59 182.515,55.887 ; 182.515,58.346 183.218,58.698 183.921,58.346 183.569,59.049 183.921,59.752 183.218,59.4 182.515,59.752 182.866,59.049 182.515,58.346 ; 182.515,61.86 182.866,61.86 183.218,61.509 183.569,61.86 183.921,61.86 183.569,62.211 183.921,62.563 183.569,62.563 183.218,62.914 182.866,62.563 182.515,62.563 182.866,62.211 182.515,61.86 ; 182.515,66.076 183.921,66.076 183.218,64.671 182.515,66.076 ; 182.515,68.185 182.866,68.185 182.866,67.833 183.569,67.833 183.569,68.185 183.921,68.185 183.921,68.887 183.569,68.887 183.569,69.239 182.866,69.239 182.866,68.887 182.515,68.887 182.515,68.185 ; 182.515,70.996 182.515,71.347 182.866,71.698 182.515,72.05 182.515,72.401 182.866,72.401 183.218,72.05 183.569,72.401 183.921,72.401 183.921,72.05 183.569,71.698 183.921,71.347 183.921,70.996 183.569,70.996 183.218,71.347 182.866,70.996 182.515,70.996
  lines w0.305: 181.241,47.911 263.339,47.911 ; 181.241,73.209 263.339,73.209 ; 189.827,44.748 189.827,76.371 ; 198.263,44.748 198.263,76.371 ; 214.43,44.748 214.43,76.371 ; 221.014,44.748 221.014,76.371 ; 230.545,44.748 230.545,76.371 ; 248.948,44.748 248.948,76.371 ; 181.241,44.748 263.339,44.748 263.339,76.371 181.241,76.371 181.241,44.748
  text "Symbol" at 183.138,74.158 h1.83
  text "Quantity" at 190.775,74.158 h1.83
  text "Finished Hole Size" at 199.212,74.158 h1.83
  text "Plated" at 215.379,74.158 h1.83
  text "Hole Type" at 221.962,74.158 h1.83
  text "Drill Layer Pair" at 231.493,74.158 h1.83
  text "Hole Tolerance" at 249.897,74.158 h1.83
  text "9" at 190.775,70.996 h1.52
  text "125.98mil (3.200mm)" at 199.212,70.996 h1.52
  text "NPTH" at 215.379,70.996 h1.52
  text "Round" at 221.962,70.996 h1.52
  text "Top Layer - Bottom Layer" at 231.493,70.996 h1.52
  text "177" at 190.775,67.833 h1.52
  text "11.81mil (0.300mm)" at 199.212,67.833 h1.52
  text "PTH" at 215.379,67.833 h1.52
  text "Round" at 221.962,67.833 h1.52
  text "Top Layer - Bottom Layer" at 231.493,67.833 h1.52
  text "1" at 190.775,64.671 h1.52
  text "15.75mil (0.400mm)" at 199.212,64.671 h1.52
  text "PTH" at 215.379,64.671 h1.52
  text "Round" at 221.962,64.671 h1.52
  text "Top Layer - Bottom Layer" at 231.493,64.671 h1.52
  text "172" at 190.775,61.509 h1.52
  text "16.00mil (0.406mm)" at 199.212,61.509 h1.52
  text "PTH" at 215.379,61.509 h1.52
  text "Round" at 221.962,61.509 h1.52
  text "Top Layer - Bottom Layer" at 231.493,61.509 h1.52
  text "341" at 190.775,58.346 h1.52
  text "19.69mil (0.500mm)" at 199.212,58.346 h1.52
  text "PTH" at 215.379,58.346 h1.52
  text "Round" at 221.962,58.346 h1.52
  text "Top Layer - Bottom Layer" at 231.493,58.346 h1.52
  text "4" at 190.775,55.184 h1.52
  text "63.00mil (1.600mm)" at 199.212,55.184 h1.52
  text "PTH" at 215.379,55.184 h1.52
  text "Round" at 221.962,55.184 h1.52
  text "Top Layer - Bottom Layer" at 231.493,55.184 h1.52
  text "2" at 190.775,52.022 h1.52
  text "188.00mil (4.775mm)" at 199.212,52.022 h1.52
  text "PTH" at 215.379,52.022 h1.52
  text "Round" at 221.962,52.022 h1.52
  text "Top Layer - Bottom Layer" at 231.493,52.022 h1.52
  text "2" at 190.775,48.859 h1.52
  text "254.00mil (6.452mm)" at 199.212,48.859 h1.52
  text "PTH" at 215.379,48.859 h1.52
  text "Round" at 221.962,48.859 h1.52
  text "Top Layer - Bottom Layer" at 231.493,48.859 h1.52
  text "708 Total" at 190.775,45.697 h1.52
  text ".Layer_Name" at 8.306,-53.556 h1.52
M17 Embedded Cavity:
  text ".Layer_Name" at 8.306,-53.556 h1.52
M18 Embedded Assembly:
  text ".Layer_Name" at 8.306,-53.556 h1.52
M19 Embedded Keepout:
  text ".Layer_Name" at 8.306,-53.556 h1.52

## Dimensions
0,0 to 156.21,0 on M2 Board Dimensions
0,0 to 0,130.81 on M2 Board Dimensions
182.65,-40.91 to 208.05,-40.91 on M2 Board Dimensions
